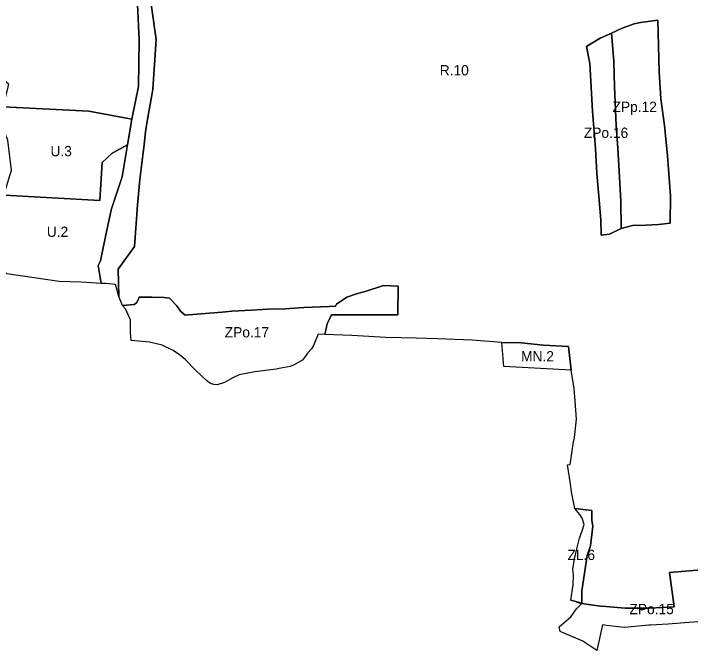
# Model space of a CAD drawing. Extents: x 7418114 to 7422197, y 5546299 to 5548348.
# Drawn here: x 7419162 to 7419820, y 5546427 to 5547046 of the extents above; entities that cross this region are included whole.
import ezdxf

# ---------------------------------------------------------------- set-up
doc = ezdxf.new("R2010")
doc.units = 0
doc.layers.add('linie_rozgraniczajace', color=7, linetype='Continuous')
doc.layers.add('oznaczenia_przeznaczen', color=7, linetype='Continuous')

msp = doc.modelspace()

# ---------------------------------------------------------------- linework, layer by layer
at = {"layer": 'linie_rozgraniczajace'}
for points in [[(7419055.24, 5547099.33), (7419103.29, 5547113.48), (7419153.9, 5547140.97), (7419172.36, 5547167.76), (7419185.81, 5547192.23), (7419213.15, 5547176.13), (7419238.55, 5547160.54), (7419252.8, 5547139.9), (7419263.1, 5547113.97), (7419272.38, 5547088.56), (7419278.12, 5547069.72), (7419279.31, 5547065.91), (7419282.99, 5547054.52), (7419284.49, 5547020.27), (7419283.78, 5546974.77), (7419277.33, 5546943.21), (7419235.6, 5546950.9), (7419203.81, 5546952.4), (7419152.36, 5546955.08), (7419152.36, 5546955.08), (7419157.99, 5546976.72), (7419139.33, 5546992.58), (7419113.59, 5547002.94), (7419101.14, 5547000.37)], [(7419719.33, 5547013.77), (7419722.63, 5546997.06), (7419725.23, 5546950.97), (7419728.08, 5546914.68), (7419729.39, 5546890.27), (7419731.29, 5546868.33), (7419733.25, 5546845.21), (7419733.66, 5546830.24), (7419741.82, 5546831.43), (7419752.93, 5546836.79), (7419764.04, 5546839.79), (7419777.03, 5546840.16), (7419789.24, 5546840.85), (7419800.68, 5546841.95), (7419801.05, 5546868.59), (7419798.02, 5546907.55), (7419795.28, 5546937.06), (7419791.51, 5546962.97), (7419790.1, 5546989.47), (7419788.63, 5547039.37), (7419771.89, 5547037.01), (7419765.65, 5547035.67), (7419754.14, 5547031.62), (7419743.63, 5547026.6), (7419732.58, 5547021.81)], [(7419743.63, 5547026.6), (7419754.14, 5547031.62), (7419765.65, 5547035.67), (7419771.89, 5547037.01), (7419788.63, 5547039.37), (7419790.1, 5546989.47), (7419791.51, 5546962.97), (7419795.28, 5546937.06), (7419798.02, 5546907.55), (7419801.05, 5546868.59), (7419800.68, 5546841.95), (7419789.24, 5546840.85), (7419777.03, 5546840.16), (7419764.04, 5546839.79), (7419752.93, 5546836.79), (7419752.71, 5546863.07), (7419751.42, 5546886.66), (7419749.67, 5546915), (7419748.16, 5546937), (7419746.66, 5546974.61), (7419745.83, 5546999.1)], [(7419719.33, 5547013.77), (7419732.58, 5547021.81), (7419743.63, 5547026.6), (7419745.83, 5546999.1), (7419746.66, 5546974.61), (7419748.16, 5546937), (7419749.67, 5546915), (7419751.42, 5546886.66), (7419752.71, 5546863.07), (7419752.93, 5546836.79), (7419741.82, 5546831.43), (7419733.66, 5546830.24), (7419733.25, 5546845.21), (7419731.29, 5546868.33), (7419729.39, 5546890.27), (7419728.08, 5546914.68), (7419725.23, 5546950.97), (7419722.63, 5546997.06)], [(7419149.33, 5546940.91), (7419152.36, 5546955.08), (7419203.81, 5546952.4), (7419235.6, 5546950.9), (7419277.33, 5546943.21), (7419273.15, 5546918.1), (7419258.35, 5546910.12), (7419248.53, 5546901.11), (7419246.21, 5546863.92), (7419153.67, 5546869.15), (7419153.67, 5546869.15), (7419154.23, 5546873.56), (7419160.3, 5546893.5), (7419156.86, 5546922.85)], [(7419138.12, 5546826.06), (7419144.94, 5546851.46), (7419152.53, 5546860.27), (7419153.67, 5546869.15), (7419246.21, 5546863.92), (7419248.53, 5546901.11), (7419258.35, 5546910.12), (7419273.15, 5546918.1), (7419267.98, 5546886.98), (7419257.46, 5546855.11), (7419257.36, 5546854.65), (7419252.09, 5546830.77), (7419246.99, 5546805.46), (7419244.53, 5546800.86), (7419247.68, 5546783.54), (7419228.22, 5546784.6), (7419206.88, 5546785.49), (7419155.81, 5546792.74), (7419142.27, 5546806.68)], [(7419268.3, 5546762.08), (7419279.55, 5546762.97), (7419282.05, 5546764.71), (7419283.71, 5546767.65), (7419284.5, 5546770.19), (7419296.88, 5546770), (7419308.92, 5546769.82), (7419313.99, 5546769.15), (7419320.73, 5546762), (7419325.05, 5546756.25), (7419329.2, 5546752.75), (7419332.44, 5546753.01), (7419365.14, 5546755.67), (7419374.63, 5546756.44), (7419393.8, 5546757.49), (7419409.13, 5546758.34), (7419426.6, 5546758.93), (7419444.6, 5546760.25), (7419469.33, 5546761), (7419475.36, 5546761.26), (7419476.26, 5546763.24), (7419486.52, 5546770.2), (7419496.62, 5546773.74), (7419504.2, 5546775.64), (7419522.03, 5546781.33), (7419536.26, 5546780.87), (7419535.99, 5546752.9), (7419534.35, 5546752.92), (7419471.54, 5546752.84), (7419467.3, 5546744.36), (7419465.07, 5546733.92), (7419458.5, 5546734.26), (7419454.12, 5546723.32), (7419451.92, 5546720.02), (7419448.08, 5546715.73), (7419443.56, 5546709.4), (7419435.24, 5546704.48), (7419431.27, 5546702.92), (7419420.67, 5546700.91), (7419417.6, 5546700.32), (7419397.1, 5546697.62), (7419381.81, 5546694.71), (7419376.85, 5546692.56), (7419375.44, 5546691.92), (7419367.44, 5546687.14), (7419360.37, 5546684.81), (7419357.01, 5546685.23), (7419353.75, 5546686.36), (7419350.21, 5546688.79), (7419339.35, 5546699.36), (7419329.49, 5546709.23), (7419324.56, 5546713.4), (7419317.55, 5546718.3), (7419306.97, 5546723.63), (7419294.6, 5546726.53), (7419276.87, 5546728.14), (7419276.28, 5546735.79), (7419276.02, 5546748.26), (7419271.42, 5546758.78)], [(7419637.17, 5546726.18), (7419655.73, 5546725.7), (7419677.64, 5546723.66), (7419701.73, 5546722.2), (7419704.37, 5546699.38), (7419639.02, 5546702.8)], [(7419704.08, 5546475.76), (7419706.3, 5546490.7), (7419706.81, 5546500.31), (7419705.97, 5546505.7), (7419707.55, 5546515.93), (7419709.53, 5546524.24), (7419712.65, 5546536.07), (7419715.28, 5546543.23), (7419717, 5546549.35), (7419715.26, 5546555.3), (7419713, 5546559.1), (7419707.92, 5546564.87), (7419724.45, 5546562.83), (7419724.45, 5546553.03), (7419725.66, 5546547.61), (7419723.37, 5546528.65), (7419719.89, 5546519.26), (7419714.75, 5546484.71), (7419714.71, 5546472.93)]]:
    msp.add_lwpolyline(points, close=True, dxfattribs=at)
for points in [[(7419292.16, 5547082.68), (7419300.96, 5547020.44), (7419297.79, 5546972.38), (7419297.65, 5546970.18), (7419296.77, 5546966.48), (7419292.23, 5546941.16), (7419290.86, 5546930.66), (7419289.25, 5546918.47), (7419286.43, 5546894.94), (7419285.17, 5546884.37), (7419282.97, 5546859.6), (7419280, 5546819.41), (7419264.1, 5546797.21), (7419264.93, 5546770.73), (7419261.49, 5546782.42), (7419252.36, 5546783.29), (7419247.68, 5546783.54), (7419244.53, 5546800.86), (7419246.99, 5546805.46), (7419252.09, 5546830.77), (7419257.36, 5546854.65), (7419257.46, 5546855.11), (7419267.98, 5546886.98), (7419273.15, 5546918.1), (7419277.33, 5546943.21), (7419283.78, 5546974.77), (7419284.49, 5547020.27), (7419282.99, 5547054.52)], [(7419842.35, 5546506.08), (7419799.96, 5546502.72), (7419804.52, 5546469.4), (7419780.74, 5546467.84), (7419757.01, 5546467.97), (7419738.23, 5546469.56), (7419732.85, 5546470.02), (7419716.67, 5546472.32), (7419714.71, 5546472.93), (7419714.75, 5546484.71), (7419719.89, 5546519.26), (7419723.37, 5546528.65), (7419725.66, 5546547.61), (7419724.45, 5546553.03), (7419724.45, 5546562.83), (7419707.92, 5546564.87), (7419704.94, 5546581.04), (7419703.89, 5546588.64), (7419700.99, 5546607.18), (7419703.59, 5546607.43), (7419706.89, 5546629.58), (7419707.65, 5546633.66), (7419709.59, 5546651.74), (7419708.22, 5546669.16), (7419707.5, 5546681.5), (7419704.37, 5546699.38), (7419701.73, 5546722.2), (7419677.64, 5546723.66), (7419655.73, 5546725.7), (7419637.17, 5546726.18), (7419608.18, 5546728.21), (7419574.7, 5546729.54), (7419553.75, 5546730.16), (7419524.42, 5546731.03), (7419491.18, 5546732.77), (7419465.07, 5546733.92), (7419467.3, 5546744.36), (7419471.54, 5546752.84), (7419534.35, 5546752.92), (7419535.99, 5546752.9), (7419536.26, 5546780.87), (7419522.03, 5546781.33), (7419504.2, 5546775.64), (7419496.62, 5546773.74), (7419486.52, 5546770.2), (7419476.26, 5546763.24), (7419475.36, 5546761.26), (7419469.33, 5546761), (7419444.6, 5546760.25), (7419426.6, 5546758.93), (7419409.13, 5546758.34), (7419393.8, 5546757.49), (7419374.63, 5546756.44), (7419365.14, 5546755.67), (7419332.44, 5546753.01), (7419329.2, 5546752.75), (7419325.05, 5546756.25), (7419320.73, 5546762), (7419313.99, 5546769.15), (7419308.92, 5546769.82), (7419296.88, 5546770), (7419284.5, 5546770.19), (7419283.71, 5546767.65), (7419282.05, 5546764.71), (7419279.55, 5546762.97), (7419268.3, 5546762.08), (7419264.93, 5546770.73), (7419264.1, 5546797.21), (7419280, 5546819.41), (7419282.97, 5546859.6), (7419285.17, 5546884.37), (7419286.43, 5546894.94), (7419289.25, 5546918.47), (7419290.86, 5546930.66), (7419292.23, 5546941.16), (7419296.77, 5546966.48), (7419297.65, 5546970.18), (7419297.79, 5546972.38), (7419300.96, 5547020.44), (7419292.16, 5547082.68)], [(7419827.5, 5546454.64), (7419810.71, 5546453.38), (7419798.72, 5546452.47), (7419781.49, 5546451.51), (7419780.06, 5546451.42), (7419755.83, 5546449.07), (7419738.81, 5546451.21), (7419734.79, 5546451.8), (7419729.31, 5546426.88), (7419715.88, 5546436.05), (7419693.89, 5546445.3), (7419692.82, 5546449.7), (7419704.19, 5546459.66), (7419709.72, 5546467.26), (7419714.66, 5546472.06), (7419704.08, 5546475.76), (7419714.71, 5546472.93), (7419716.67, 5546472.32), (7419732.85, 5546470.02), (7419738.23, 5546469.56), (7419757.01, 5546467.97), (7419780.74, 5546467.84), (7419804.52, 5546469.4), (7419799.96, 5546502.72), (7419842.35, 5546506.08)]]:
    msp.add_lwpolyline(points, dxfattribs=at)

# ---------------------------------------------------------------- texts
at = {"layer": 'oznaczenia_przeznaczen'}
for s, p in [('R.10', (7419576.72, 5546985.64)), ('ZPp.12', (7419744.66, 5546950.09)), ('ZPo.16', (7419716.8, 5546924.91)), ('U.3', (7419198.32, 5546907.09)), ('U.2', (7419194.75, 5546828.74)), ('ZPo.17', (7419367.71, 5546731.08)), ('MN.2', (7419655.76, 5546707.73)), ('ZL.6', (7419700.91, 5546514.75)), ('ZPo.15', (7419761.11, 5546462.12))]:
    msp.add_text(s, height=10, dxfattribs=at).set_placement(p)

doc.saveas('drawing.dxf')
